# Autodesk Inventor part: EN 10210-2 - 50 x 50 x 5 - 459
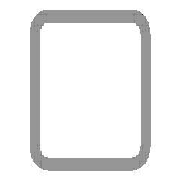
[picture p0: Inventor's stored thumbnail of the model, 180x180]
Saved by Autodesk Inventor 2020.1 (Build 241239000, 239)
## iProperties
Created: 2019-10
Part Number: EN 10210-2 - 50 x 50 x 5 - 459
Material: Stahl, weich
Description: Rohrleitung
Document SubType Name: Modeling
Standard: DIN
Designer: lutzd
Standard Revision: 2006-07
Standards Organization: DIN
Language: de-DE
Size Designation: 50 x 50 x 5
Categories: <MemberInstance><Categories><Category DisplayName="Profile" InternalName="089c4875-fa83-4c05-b084-43b9cc11f5ed" Mnemonic="GRDR"><CategoryParameter DisplayName="
Stock Number: 50 x 50 x 5
Mass: 3146.18 g
Surface Area: 1571.36 cm^2
Volume: 400.787 cm^3
Density: 7.85 g/cm^3
Appearance: Halbpoliert
IsCustomPart: 1
G_W: 50,000 mm
G_H: 50,000 mm
Dimensions: 50x50x459 mm
Mass: 3,146 kg
DocNumber: ADSK-014209
Folder: .
+9198FFB3-0B6D-4C87-A09E-8D31B20E3740+SCHNITTDETAIL1: Schnittwinkel 90,00 grd
+12A15BAA-37E3-4230-BC92-45040C826AB4+SCHNITTDETAIL2: Schnittwinkel 90,00 grd
G_L: 459,000 mm
_CCFamilyMember: 16
_CCFamilyDisplayName: DIN EN 10210-2 (USAS B17.1 quadratisch) - Rohrleitung — In Klammern angegebene Größen wurden aufgehoben
_FrameMemberDoc: Frame Member File
_Version: 15.0.0
_GetPNFromCC: 1
Title: Profil-Bauteil
Author: lutzd
Revision Number: -
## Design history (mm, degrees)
node "Startebene"
node "Endebene"
sketch "Skizze"
  geometry: L1 (-25, -17.5)-(-25, 17.5); L2 (-17.5, 25)-(17.5, 25); L3 (25, 17.5)-(25, -17.5); L4 (17.5, -25)-(-17.5, -25); L5 (-15, 20)-(15, 20); L6 (20, 15)-(20, -15); L7 (15, -20)-(-15, -20); L8 (-20, -15)-(-20, 15); L9 (0, 37.175)-(0, -37.175) reference; L10 (-37.175, 0)-(37.175, 0) reference; A1 r 7.5 centre (-17.5, -17.5) between (-25, -17.5) and (-17.5, -25); A2 r 7.5 centre (-17.5, 17.5) between (-17.5, 25) and (-25, 17.5); A3 r 7.5 centre (17.5, 17.5) between (25, 17.5) and (17.5, 25); A4 r 7.5 centre (17.5, -17.5) between (17.5, -25) and (25, -17.5); A5 r 5 centre (-15, -15) between (-20, -15) and (-15, -20); A6 r 5 centre (-15, 15) between (-15, 20) and (-20, 15); A7 r 5 centre (15, 15) between (20, 15) and (15, 20); A8 r 5 centre (15, -15) between (15, -20) and (20, -15)
  constraints: 16 end point, 16 point on circle, 16 tangent, 8 centre point, 6 equal radius, 4 parallel, 2 perpendicular, 2 other
  dimensions: "d7" = 7.5 radius of A1 (= G_IR); "d10" = 50 distance between parallel lines of L2 L4 (= G_H); "d11" = 50 distance between parallel lines of L1 L3 (= G_W); "d12" = 5 distance between parallel lines of L3 L6 (= G_T); "d15" = 25 distance between parallel lines of L2 L10 (= 0.5 x d10); "d16" = 25 distance between parallel lines of L9 L3 (= 0.5 x d11); "d19" = 5 radius of A5 (= G_T); "d20" = 5 distance between parallel lines of L4 L7 (= G_T)
extrude "Körper" new body sketch "Skizze" stored distance "d3" = 459 (= G_L); taper "d4" = 0 deg
node "Driven Length"
  sketch "Sketch3"
    geometry: L1 (0, 0)-(10, 0) reference
    constraints: 2 end point, 1 horizontal
  workplane "Work Plane3"
  sketch "Sketch4"
    geometry: L1 (-2, 50)-(12, 50) reference; L2 (-2, 509)-(12, 509) reference
    dimensions: "d18" = 459 distance between parallel lines of L1 L2 (derived)
workplane "Arbeitsebene4"
feature "Trennen1"
workplane "Arbeitsebene5"
feature "Trennen2"
body "Solid1"
other parameters: "G_W" = 50 [user parameter; used in 1 equation term], "G_H" = 50 [user parameter; used in 1 equation term], "G_T" = 5 [user parameter; used in 3 equation terms], "G_IR" = 7.5 [user parameter; used in 1 equation term], "G_L" = 459 (= d18) [user parameter; used in 1 equation term], "d14" = 509 (= G_OFFSET_END + B_L), "B_L" = 559 [user parameter; used in 1 equation term], "d17" = 90 deg
